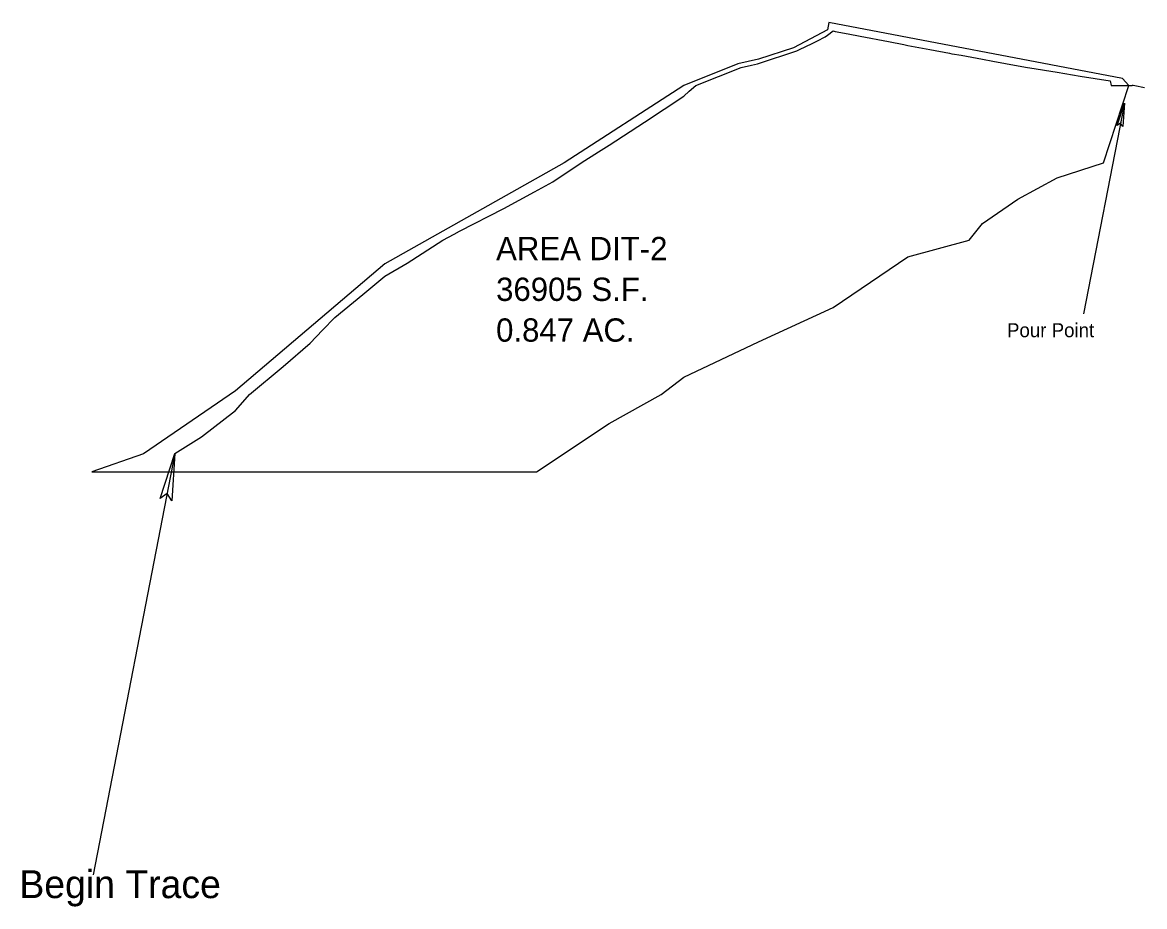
# Model space of a CAD drawing. Extents: x 3141 to 5445, y 2679 to 3371.
import ezdxf

# ---------------------------------------------------------------- set-up
doc = ezdxf.new("R2010")
doc.units = 0
for name, color, linetype in [('DESIGN - SCRATCH - User 1', 7, 'Continuous'), ('SURVEY - CENTERLINE - Preliminary', 7, 'Continuous'), ('SURVEY - CENTERLINE - Preliminary Text', 7, 'Continuous'), ('SURVEY - DRAINAGE - Area Shapes', 7, 'Continuous')]:
    doc.layers.add(name, color=color, linetype=linetype)

msp = doc.modelspace()

# ---------------------------------------------------------------- linework, layer by layer
at = {"layer": 'DESIGN - SCRATCH - User 1'}
msp.add_line((3614.07, 3024.35), (3596.53, 2933.9), dxfattribs=at)
msp.add_lwpolyline([(3614.07, 3024.35), (3613.38, 3014.24), (3612.4, 3015.76), (3610.88, 3014.73)], close=True, dxfattribs=at)
msp.add_lwpolyline([(3614.07, 3024.35), (3613.38, 3014.24), (3612.4, 3015.76), (3610.88, 3014.73), (3614.07, 3024.35)], dxfattribs=at)
at = {"layer": 'SURVEY - CENTERLINE - Preliminary'}
msp.add_lwpolyline([(3206.4, 2873.8), (3217.81, 2881.03), (3232.39, 2892.35), (3235.5, 2895.92), (3238.34, 2899.13), (3252.79, 2911.21), (3264.47, 2921.22), (3269.78, 2926.82), (3275.08, 2932.32), (3287.02, 2942.17), (3296.54, 2950.03), (3306.15, 2955.57), (3321.36, 2965.51), (3326.23, 2967.98), (3328.62, 2969.32), (3347.55, 2979.11), (3360.7, 2986.24), (3368.62, 2990.5), (3380.74, 2998.69), (3388.27, 3003.35), (3392.78, 3006.24), (3407.93, 3016.2), (3424.85, 3027.37), (3427.24, 3029.41), (3430.05, 3031.88), (3449.46, 3039.61), (3454, 3040.67), (3455.18, 3040.95), (3456.54, 3041.26), (3456.93, 3041.37), (3473.41, 3046.7), (3474.27, 3047.13), (3477.54, 3048.75), (3479.63, 3049.8), (3482.22, 3051.11), (3485.51, 3052.77), (3486.51, 3053.5), (3489, 3055.29), (3489.01, 3055.29), (3489.86, 3055.12), (3495.49, 3054.04), (3500.62, 3053.06), (3512.72, 3050.73), (3519.32, 3049.47), (3521.08, 3049.13), (3530.57, 3047.32), (3538.96, 3045.71), (3539.97, 3045.53), (3540.1, 3045.51), (3543.89, 3044.84), (3553.16, 3043.16), (3557.53, 3042.37), (3568.49, 3040.39), (3572.49, 3039.66), (3573.41, 3039.49), (3585.13, 3037.58), (3595.06, 3035.96), (3607.96, 3033.86), (3608.32, 3031.88), (3617.32, 3031.88), (3617.44, 3032.08), (3617.77, 3032.02), (3618.49, 3031.88), (3622.7, 3031.07)], dxfattribs=at)
at = {"layer": 'SURVEY - CENTERLINE - Preliminary Text'}
msp.add_line((3206.4, 2873.8), (3171.33, 2692.9), dxfattribs=at)
msp.add_lwpolyline([(3206.4, 2873.8), (3205.03, 2853.59), (3203.07, 2856.62), (3200.02, 2854.56)], close=True, dxfattribs=at)
msp.add_lwpolyline([(3206.4, 2873.8), (3205.03, 2853.59), (3203.07, 2856.62), (3200.02, 2854.56), (3206.4, 2873.8)], dxfattribs=at)
at = {"layer": 'SURVEY - DRAINAGE - Area Shapes'}
for points in [[(3487.12, 3058.96), (3486.62, 3055.76), (3471.95, 3048.08), (3456.93, 3043.22), (3448, 3041.12), (3424.81, 3031.88), (3373.51, 2998.69), (3296.54, 2955.27), (3232.39, 2900.73), (3192.87, 2873.65), (3170.72, 2865.94)], [(3170.72, 2865.94), (3361.69, 2865.94), (3392.78, 2886.73), (3415.12, 2899.13), (3424.85, 2906.59), (3456.93, 2921.74), (3489.01, 2936.48), (3521.08, 2958.29), (3547.33, 2965.51), (3553.16, 2972.59), (3568.32, 2983.01), (3585.24, 2992.22), (3605.12, 2998.69), (3615.98, 3031.88), (3613.18, 3034.84), (3487.12, 3058.96)]]:
    msp.add_lwpolyline(points, dxfattribs=at)

# ---------------------------------------------------------------- texts
at = {"layer": 'DESIGN - SCRATCH - User 1'}
msp.add_text('Pour Point', height=6, dxfattribs=at).set_placement((3563.63, 2923.8))
at = {"layer": 'SURVEY - CENTERLINE - Preliminary Text'}
msp.add_text('Begin Trace', height=12, dxfattribs=at).set_placement((3139.58, 2682.91))
at = {"layer": 'SURVEY - DRAINAGE - Area Shapes'}
for s, p in [('AREA DIT-2', (3344.28, 2956.87)), ('36905 S.F.', (3344.28, 2939.37)), ('0.847 AC.', (3344.28, 2921.87))]:
    msp.add_text(s, height=10, dxfattribs=at).set_placement(p)

doc.saveas('drawing.dxf')
